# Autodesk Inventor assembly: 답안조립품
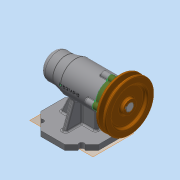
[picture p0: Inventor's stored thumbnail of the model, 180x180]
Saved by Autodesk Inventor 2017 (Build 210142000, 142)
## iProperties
Created: 2019-12
Part Number: 답안조립품
Document SubType Name: Assembly
Designer: 5-05-le
Author: 5-05-le
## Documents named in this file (12)
- C:\Users\5-05-le\Desktop\491204V1034\답안조립품.iam
- C:\Users\5-05-le\Desktop\491204V1034\본체.ipt
- C:\Users\5-05-le\Desktop\491204V1034\Ű 5 x 5 x 16.ipt
- C:\Users\5-05-le\Desktop\491204V1034\V벨트풀리.ipt
- C:\Users\5-05-le\Desktop\491204V1034\멈춤나사 M3.ipt
- C:\Users\5-05-le\Desktop\491204V1034\베어링 6004.ipt
- C:\Users\5-05-le\Desktop\491204V1034\베어링 51202.ipt
- C:\Users\5-05-le\Desktop\491204V1034\볼트 M4.ipt
- C:\Users\5-05-le\Desktop\491204V1034\어댑터슬리브.ipt
- C:\Users\5-05-le\Desktop\491204V1034\오일 실.ipt
- C:\Users\5-05-le\Desktop\491204V1034\축.ipt
- C:\Users\5-05-le\Desktop\491204V1034\커버.ipt
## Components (2 placed, 2 different names)
1. Ű 5 x 5 x 16:1 — 각도:1, 각도:2
2. V벨트풀리:1 — 각도:2
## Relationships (2: Angle 2)
- 각도:1 [Angle]: Ű 5 x 5 x 16:1
- 각도:2 [Angle]: Ű 5 x 5 x 16:1 ↔ V벨트풀리:1
